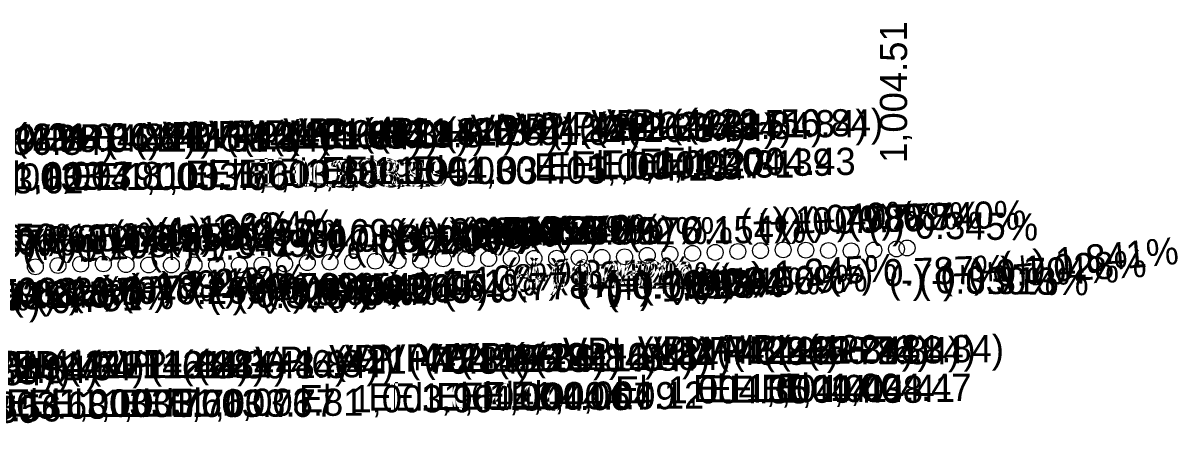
# Model space of a CAD drawing. Extents: x 16972137 to 16976737, y 12558490 to 12559551.
# Drawn here: x 16976482 to 16976736.8, y 12558922.2 to 12559011.4 of the extents above; entities that cross this region are included whole.
import ezdxf

# ---------------------------------------------------------------- set-up
doc = ezdxf.new("R2010")
doc.units = 0
doc.layers.add('RD_DDB_GradeTX', color=7, linetype='Continuous')
doc.layers.add('RD_DDB_PI', color=7, linetype='Continuous')

msp = doc.modelspace()

# ---------------------------------------------------------------- linework, layer by layer
at = {"layer": 'RD_DDB_PI'}
for centre in [(16976644.74, 12558961.27), (16976649.74, 12558961.46), (16976654.74, 12558961.37), (16976659.74, 12558961.29), (16976664.74, 12558961.21), (16976669.74, 12558961.39), (16976674.74, 12558961.64), (16976677.07, 12558961.86), (16976549.74, 12558958.74), (16976554.74, 12558958.85), (16976559.74, 12558958.96), (16976564.74, 12558959.04), (16976569.74, 12558959.11), (16976574.74, 12558959.45), (16976579.74, 12558959.47), (16976584.74, 12558959.49), (16976589.74, 12558959.51), (16976594.74, 12558959.56), (16976599.74, 12558959.59), (16976604.74, 12558959.68), (16976609.74, 12558959.79), (16976614.74, 12558959.91), (16976619.74, 12558960.22), (16976624.74, 12558960.48), (16976629.74, 12558960.68), (16976634.74, 12558960.88), (16976639.74, 12558961.08), (16976484.74, 12558957.69), (16976489.74, 12558958), (16976494.74, 12558958.29), (16976499.74, 12558958.35), (16976504.74, 12558958.18), (16976509.74, 12558958.1), (16976514.74, 12558958.11), (16976519.74, 12558958.13), (16976524.74, 12558958.12), (16976529.74, 12558958.09), (16976534.74, 12558958.15), (16976539.74, 12558958.34), (16976544.74, 12558958.62)]:
    msp.add_circle(centre, 1.75, dxfattribs=at)

# ---------------------------------------------------------------- texts
at = {"layer": 'RD_DDB_GradeTX'}
for s, rotation, p in [('(+) 1.040%', 2.9768, (16976640.33, 12558964.3)), ('(+) 0.798%', 2.2855, (16976644.02, 12558964.26)), ('(+) 0.788%', 2.2566, (16976648.9, 12558964.44)), ('(+) 0.778%', 2.2276, (16976654.2, 12558964.64)), ('(+) 0.740%', 2.12, (16976664.03, 12558964.99)), ('(+) 1.196%', 3.4227, (16976502.06, 12558961.74)), ('(+) 1.124%', 3.2161, (16976511.72, 12558962.24)), ('(+) 0.092%', 0.2624, (16976513.61, 12558962.17)), ('(+) 0.277%', 0.7937, (16976514.05, 12558961.55)), ('(+) 0.169%', 0.4835, (16976530.6, 12558962.01)), ('(+) 1.040%', 2.9768, (16976560.44, 12558960.15)), ('(+) 0.798%', 2.2855, (16976564.08, 12558961.07)), ('(+) 0.470%', 1.3471, (16976564.07, 12558962.08)), ('(+) 0.448%', 1.2819, (16976568.9, 12558962.17)), ('(+) 0.788%', 2.2566, (16976568.97, 12558961.29)), ('(+) 0.425%', 1.2167, (16976573.43, 12558962.25)), ('(+) 0.358%', 1.0258, (16976578.27, 12558962.29)), ('(+) 0.787%', 2.2525, (16976579.26, 12558961.7)), ('(+) 0.265%', 0.7604, (16976583.46, 12558962.29)), ('(+) 0.740%', 2.12, (16976584.08, 12558962.03)), ('(+) 0.092%', 0.2624, (16976593.61, 12558962.53)), ('(+) 0.076%', 0.2168, (16976599.14, 12558962.54)), ('(+) 0.154%', 0.4413, (16976615.37, 12558962.71)), ('(-) 0.345%', 359.0114, (16976668.49, 12558964.13)), ('(+) 0.684%', 1.9574, (16976448.86, 12558958.79)), ('(+) 0.657%', 1.8825, (16976453.92, 12558958.93)), ('(+) 0.067%', 0.1931, (16976454.14, 12558960.91)), ('(-) 0.056%', 359.8391, (16976458.75, 12558961.3)), ('(+) 0.863%', 2.4706, (16976468.41, 12558959.74)), ('(+) 0.851%', 2.4373, (16976475.13, 12558960.02)), ('(+) 1.108%', 3.1702, (16976481.97, 12558958.15)), ('(+) 0.470%', 1.3471, (16976484.1, 12558960.19)), ('(+) 0.448%', 1.2819, (16976488.92, 12558960.38)), ('(+) 0.425%', 1.2167, (16976493.45, 12558960.55)), ('(+) 0.358%', 1.0258, (16976498.28, 12558960.86)), ('(+) 1.342%', 3.84, (16976509.92, 12558958.1)), ('(-) 0.690%', 358.0253, (16976519.07, 12558960.69)), ('(-) 0.056%', 359.8391, (16976538.75, 12558961.08)), ('(-) 0.088%', 359.7485, (16976543.75, 12558961.03)), ('(+) 1.245%', 3.5629, (16976555.09, 12558959.21)), ('(+) 1.841%', 5.2596, (16976697.89, 12558954.74)), ('(+) 1.245%', 3.5629, (16976635.67, 12558952.2)), ('(+) 1.028%', 2.9425, (16976690.59, 12558953.45)), ('(+) 1.242%', 3.5532, (16976505.56, 12558949.97)), ('(+) 1.108%', 3.1702, (16976562.51, 12558950.59)), ('(-) 0.345%', 359.0114, (16976588.3, 12558953.52)), ('(+) 1.342%', 3.84, (16976590.53, 12558951.49)), ('(-) 0.330%', 359.0559, (16976593.01, 12558953.39)), ('(-) 0.313%', 359.1044, (16976599.67, 12558953.23)), ('(+) 0.509%', 1.4584, (16976628.96, 12558951.27)), ('(+) 0.787%', 2.2525, (16976659.67, 12558952.85)), ('(-) 0.330%', 359.0559, (16976673, 12558952.07)), ('(-) 0.313%', 359.1044, (16976679.66, 12558951.98)), ('(+) 0.704%', 2.0164, (16976684.46, 12558952.9)), ('(-) 0.088%', 359.7485, (16976463.7, 12558949.38)), ('(+) 1.022%', 2.9245, (16976465.35, 12558947.72)), ('(+) 0.870%', 2.4914, (16976479.41, 12558948.21)), ('(+) 0.877%', 2.51, (16976484.7, 12558948.44)), ('(+) 1.189%', 3.4011, (16976492.66, 12558949.14)), ('(+) 1.211%', 3.465, (16976498.96, 12558949.54)), ('(+) 0.265%', 0.7604, (16976503.63, 12558949.23)), ('(+) 0.076%', 0.2168, (16976519.19, 12558950.24)), ('(+) 0.099%', 0.2848, (16976524.02, 12558950.19)), ('(+) 0.045%', 0.1295, (16976528.76, 12558949.14)), ('(+) 0.067%', 0.1931, (16976534.18, 12558949.18)), ('(+) 0.154%', 0.4413, (16976535.46, 12558950.1)), ('(+) 0.362%', 1.0383, (16976538.5, 12558949.48)), ('(+) 0.406%', 1.1637, (16976544.17, 12558949.45)), ('(+) 0.248%', 0.709, (16976548.73, 12558949.33)), ('(+) 0.509%', 1.4584, (16976548.99, 12558949.24)), ('(+) 0.751%', 2.1499, (16976555.89, 12558949.94)), ('(+) 0.778%', 2.2276, (16976574.73, 12558949.54)), ('(+) 0.099%', 0.2848, (16976604.02, 12558950.58)), ('(+) 0.704%', 2.0164, (16976604.51, 12558950.08)), ('(+) 1.028%', 2.9425, (16976610.7, 12558949.34)), ('(+) 0.169%', 0.4835, (16976610.7, 12558950.69)), ('(+) 0.362%', 1.0383, (16976618.48, 12558950.93)), ('(+) 0.406%', 1.1637, (16976624.15, 12558951.08)), ('(+) 0.736%', 2.1075, (16976444.17, 12558946.66)), ('(+) 0.045%', 0.1295, (16976448.76, 12558948.96)), ('(+) 0.835%', 2.3896, (16976458.68, 12558947.25)), ('(+) 0.248%', 0.709, (16976468.74, 12558948.34)), ('(+) 0.751%', 2.1499, (16976475.95, 12558946.94)), ('(-) 0.325%', 359.0691, (16976522.94, 12558948.89))]:
    msp.add_text(s, height=6, rotation=rotation, dxfattribs=at).set_placement(p)
at = {"layer": 'RD_DDB_PI'}
msp.add_text('1,004.51', height=6, rotation=90, dxfattribs=at).set_placement((16976677.07, 12558980.61))
for s, p in [('VPI  (422+26.84)', (16976580.79, 12558985.22)), ('VPI  (422+31.84)', (16976587.27, 12558985.48)), ('VPI  (422+36.84)', (16976590.74, 12558985.68)), ('VPI  (422+41.84)', (16976597.68, 12558985.88)), ('VPI  (422+51.84)', (16976607.45, 12558986.27)), ('VPI  (422+56.84)', (16976610.91, 12558986.46)), ('VPI  (420+86.84)', (16976441.27, 12558982.39)), ('VPI  (420+96.84)', (16976451.39, 12558983)), ('VPI  (421+01.84)', (16976459.46, 12558983.29)), ('VPI  (421+06.84)', (16976462.92, 12558983.35)), ('VPI  (421+26.84)', (16976482.68, 12558983.13)), ('VPI  (421+31.84)', (16976489.16, 12558983.12)), ('VPI  (421+51.84)', (16976509.34, 12558983.62)), ('VPI  (421+56.84)', (16976512.8, 12558983.74)), ('VPI  (421+61.84)', (16976519.57, 12558983.85)), ('VPI  (421+66.84)', (16976523.04, 12558983.96)), ('VPI  (421+71.84)', (16976529.75, 12558984.04)), ('VPI  (421+81.84)', (16976539.46, 12558984.45)), ('VPI  (421+86.84)', (16976542.92, 12558984.47)), ('VPI  (422+01.84)', (16976557.57, 12558984.56)), ('El  1,004.27', (16976603.11, 12558977.18)), ('El  1,004.31', (16976609.41, 12558977.38)), ('El  1,004.39', (16976617.87, 12558977.77)), ('El  1,004.43', (16976622.9, 12558977.96)), ('El  1,003.74', (16976463.05, 12558974.5)), ('El  1,003.79', (16976468.05, 12558974.79)), ('El  1,003.81', (16976474.29, 12558974.85)), ('El  1,003.76', (16976493.05, 12558974.63)), ('El  1,003.76', (16976498.05, 12558974.62)), ('El  1,003.86', (16976517.75, 12558975.12)), ('El  1,003.88', (16976522.66, 12558975.24)), ('El  1,003.91', (16976529.41, 12558975.35)), ('El  1,003.93', (16976532.49, 12558975.46)), ('El  1,003.95', (16976537.66, 12558975.54)), ('El  1,004.03', (16976547.78, 12558975.95)), ('El  1,004.03', (16976552.78, 12558975.97)), ('El  1,004.05', (16976567.96, 12558976.06)), ('El  1,004.18', (16976594.73, 12558976.72)), ('El  1,004.23', (16976597.55, 12558976.98)), ('El  1,003.62', (16976452.55, 12558973.89)), ('VPI  (422+61.84)', (16976617.68, 12558936.37)), ('VPI  (422+66.84)', (16976621.15, 12558936.29)), ('VPI  (422+76.84)', (16976631.33, 12558936.39)), ('VPI  (422+81.84)', (16976637.57, 12558936.64)), ('VPI  (421+76.84)', (16976533.22, 12558934.11)), ('VPI  (421+91.84)', (16976549.57, 12558934.49)), ('VPI  (421+96.84)', (16976553.04, 12558934.51)), ('VPI  (422+06.84)', (16976561.03, 12558934.59)), ('VPI  (422+11.84)', (16976569.22, 12558934.68)), ('VPI  (422+16.84)', (16976572.68, 12558934.79)), ('VPI  (422+21.84)', (16976577.33, 12558934.91)), ('VPI  (422+46.84)', (16976601.15, 12558936.08)), ('VPI  (422+71.84)', (16976627.86, 12558936.21)), ('VPI  (420+71.84)', (16976428.1, 12558931.58)), ('VPI  (420+76.84)', (16976431.56, 12558931.79)), ('VPI  (420+81.84)', (16976437.8, 12558932.09)), ('VPI  (420+91.84)', (16976447.92, 12558932.69)), ('VPI  (421+11.84)', (16976471.11, 12558933.18)), ('VPI  (421+16.84)', (16976474.57, 12558933.1)), ('VPI  (421+21.84)', (16976479.22, 12558933.11)), ('VPI  (421+36.84)', (16976492.63, 12558933.09)), ('VPI  (421+41.84)', (16976499.57, 12558933.15)), ('VPI  (421+46.84)', (16976503.04, 12558933.34)), ('El  1,004.06', (16976573.17, 12558926.09)), ('El  1,004.07', (16976578.34, 12558926.18)), ('El  1,004.09', (16976583.17, 12558926.29)), ('El  1,004.12', (16976589.5, 12558926.41)), ('El  1,004.35', (16976612.66, 12558927.58)), ('El  1,004.41', (16976629.82, 12558927.87)), ('El  1,004.40', (16976633.17, 12558927.79)), ('El  1,004.38', (16976637.78, 12558927.71)), ('El  1,004.41', (16976644.82, 12558927.89)), ('El  1,004.47', (16976648.46, 12558928.14)), ('El  1,003.56', (16976447.64, 12558923.59)), ('El  1,003.68', (16976457.78, 12558924.19)), ('El  1,003.77', (16976478.23, 12558924.68)), ('El  1,003.76', (16976483.05, 12558924.6)), ('El  1,003.76', (16976488.05, 12558924.61)), ('El  1,003.76', (16976503.05, 12558924.59)), ('El  1,003.77', (16976508.23, 12558924.65)), ('El  1,003.81', (16976514.29, 12558924.84)), ('El  1,003.96', (16976542.87, 12558925.61)), ('El  1,004.04', (16976558.17, 12558925.99)), ('El  1,004.04', (16976563.17, 12558926.01)), ('El  1,003.50', (16976442.52, 12558923.29))]:
    msp.add_text(s, height=6, dxfattribs=at).set_placement(p)

doc.saveas('drawing.dxf')
